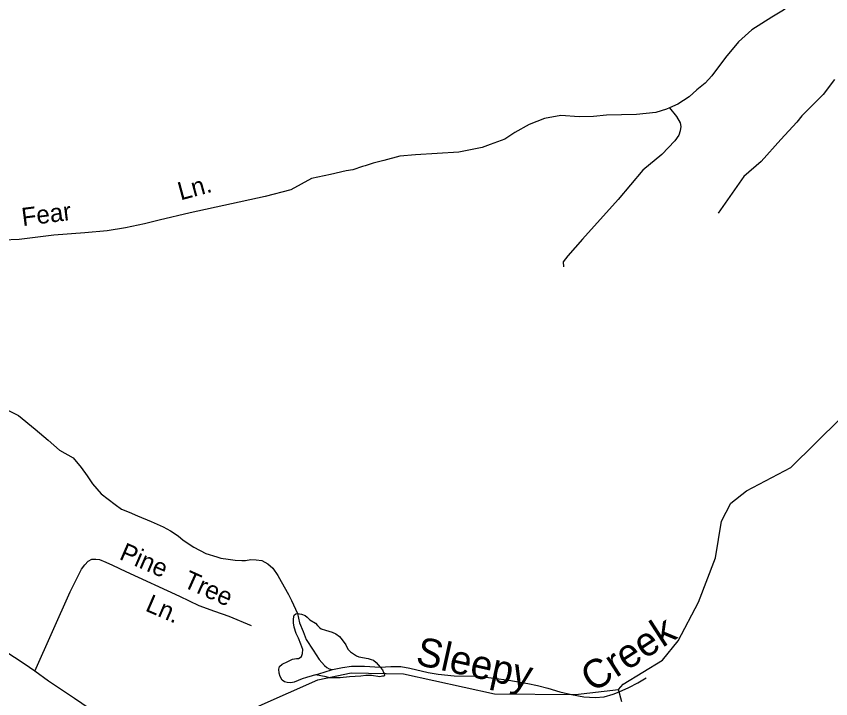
# Model space of a CAD drawing. Extents: x 2206922 to 2357709, y 510027 to 673830.
# Drawn here: x 2305011 to 2309278, y 544730 to 548303 of the extents above; entities that cross this region are included whole.
import ezdxf

# ---------------------------------------------------------------- set-up
doc = ezdxf.new("R2010")
doc.units = 0
for name, color, linetype in [('Exist Hydrographic Creek Single Shore', 7, 'Continuous'), ('Exist Hydrographic Creek Single Shore Label', 7, 'Continuous'), ('Exist Hydrographic Misc Water Feature', 7, 'Continuous'), ('Exist Road Non-System Type 51', 7, 'Continuous'), ('Exist Road Non-System Type 51 Label', 7, 'Continuous'), ('Exist Road Secondary Type 51 Attributed', 7, 'Continuous')]:
    doc.layers.add(name, color=color, linetype=linetype)

msp = doc.modelspace()

# ---------------------------------------------------------------- linework, layer by layer
at = {"layer": 'Exist Hydrographic Creek Single Shore'}
for points in [[(2308166.3, 544778), (2308190.3, 544805.2), (2308397.2, 544931.7), (2308479.2, 545033.4), (2308586.3, 545234.6), (2308675.3, 545467.9), (2308706.2, 545659.5), (2308755.2, 545753.3), (2308837.2, 545819), (2309069.4, 545939.9), (2309589.4, 546453.1), (2309837.3, 546555.1), (2310129.3, 546556.9), (2310470.3, 546544.5), (2311010.4, 546668), (2311276.3, 546760.7), (2311326.4, 546762.7)], [(2305660.2, 543918.8), (2305708.2, 544061.9), (2305749.2, 544135.7), (2305947.2, 544347.2), (2305987.2, 544440.7), (2306284.1, 544692.2), (2306591.3, 544829.3), (2306766.2, 544865.8), (2307040.2, 544860.5), (2307516.3, 544755), (2307941.2, 544752.4), (2308166.3, 544778)]]:
    msp.add_lwpolyline(points, dxfattribs=at)
at = {"layer": 'Exist Hydrographic Misc Water Feature'}
for points in [[(2304908.2, 546271), (2305022.7, 546212.4), (2305111, 546141.5), (2305178.1, 546084.4), (2305238.6, 546031.1), (2305308.9, 545991.7), (2305351.4, 545940.3), (2305381.9, 545896.4), (2305410.2, 545854.8), (2305456.8, 545803.1), (2305529.3, 545746.4), (2305563.4, 545722.6), (2305603.6, 545706.9), (2305645.8, 545687.5), (2305718.4, 545658.4), (2305780.7, 545629.1), (2305818.7, 545609.6), (2305859.1, 545582), (2305885.3, 545560.2), (2305941.5, 545522.6), (2306004, 545489.7), (2306062.3, 545472), (2306082.2, 545466.1), (2306121.9, 545460.9), (2306158, 545455.1), (2306192.3, 545453.6), (2306212.2, 545453.8), (2306240.1, 545458.1), (2306267.9, 545456.4), (2306297.9, 545452.7), (2306330.1, 545436.9), (2306354.7, 545413.3), (2306381.1, 545375.7), (2306399.2, 545343.8), (2306438.1, 545276.3), (2306452.5, 545244.5), (2306484.9, 545176.8)], [(2306578.2, 544854.1), (2306562.2, 544850), (2306532.5, 544841.6), (2306508.5, 544833.4), (2306466.6, 544817), (2306449, 544812.8), (2306431, 544814.3), (2306417.2, 544818.4), (2306404.9, 544826.3), (2306394.7, 544846.1), (2306388.7, 544864), (2306386.5, 544883.8), (2306389.9, 544897.9), (2306403.9, 544910), (2306434, 544924.5), (2306459.3, 544936.5), (2306479.6, 544940.8), (2306489.4, 544940.9), (2306499.4, 544945.1), (2306505.6, 544951), (2306511.1, 544967.2), (2306512.8, 544987.3), (2306502.7, 545015.2), (2306490.4, 545047), (2306478.3, 545070.7), (2306467.9, 545104.7), (2306463.4, 545126.5), (2306463.2, 545148.4), (2306467, 545166.5), (2306475.3, 545174.6), (2306484.9, 545176.8)], [(2306484.9, 545176.8), (2306505, 545172.9), (2306525.1, 545165.5), (2306535.3, 545157.4), (2306549.1, 545143.6), (2306579.4, 545126), (2306589.7, 545114), (2306599.5, 545101.9), (2306607.9, 545096.2), (2306631.7, 545088.6), (2306665.7, 545079), (2306685.8, 545069.1), (2306704.5, 545055.4), (2306718.4, 545037.4), (2306738.3, 545011.7), (2306748.8, 544989.8), (2306762.9, 544975.9), (2306778.9, 544964.2), (2306793.5, 544954.4), (2306805.2, 544948.5), (2306855.4, 544941), (2306871.4, 544935.3), (2306883.5, 544931), (2306897.2, 544919.2), (2306907.7, 544907.6), (2306917.5, 544895.5)], [(2306484.9, 545176.8), (2306495.8, 545126.9), (2306514, 545081.1), (2306530.4, 545039.4), (2306567.1, 544983.9), (2306597.5, 544936), (2306625.8, 544904.6), (2306638.3, 544892.5), (2306650, 544886.7), (2306668, 544882.8)], [(2306668, 544882.8), (2306720.1, 544893.6), (2306767.9, 544899.8), (2306835.9, 544900.9), (2306917.5, 544895.5)], [(2306917.5, 544895.5), (2306930.1, 544881.9), (2306936, 544868), (2306940.1, 544858), (2306940.5, 544851.9), (2306936.4, 544847.7), (2306930.5, 544847.7), (2306916.1, 544843.8), (2306872.2, 544851.2), (2306842.1, 544850.9), (2306816.3, 544848.7), (2306756.8, 544843.9), (2306708.4, 544839.4), (2306680.3, 544839.2), (2306652.2, 544838.9), (2306634.4, 544844.5), (2306578.2, 544854.1)], [(2306578.2, 544854.1), (2306624.5, 544868.7), (2306668, 544882.8)], [(2306917.5, 544895.5), (2306973.7, 544898.4), (2307025.6, 544898.7), (2307073.8, 544889.4), (2307169.8, 544866.4), (2307222.1, 544859), (2307306.1, 544850), (2307427.9, 544847.1), (2307514, 544838.1), (2307592.2, 544826.8), (2307692.2, 544810.1), (2307742.1, 544798.6), (2307796.4, 544785.1), (2307858.7, 544766), (2307920.7, 544752.6), (2307984.6, 544739.3), (2308044.5, 544736), (2308090.7, 544740.4), (2308138.4, 544753.1), (2308170.6, 544765.3), (2308220.2, 544787.8), (2308268, 544812.3), (2308311.5, 544838.6)], [(2308183.3, 544713), (2308166.3, 544778)]]:
    msp.add_lwpolyline(points, dxfattribs=at)
at = {"layer": 'Exist Road Non-System Type 51'}
for points in [[(2309382.1, 548756.2), (2309364.6, 548709), (2309341.7, 548656.4), (2309312, 548610.5), (2309307.9, 548601.9), (2309285, 548573.6), (2309227.1, 548502.6), (2309185.3, 548448.6), (2309096.3, 548383.9), (2309031.6, 548335.3), (2308969.5, 548298.9), (2308865.7, 548232.8), (2308795.6, 548169.4), (2308726.8, 548087.4), (2308655.9, 547990.7), (2308620.3, 547952.3), (2308576.7, 547917.9), (2308537.1, 547881.5), (2308477.5, 547842.9), (2308433.5, 547823.3)], [(2309298.8, 547971.3), (2309238.5, 547893.5), (2309126.7, 547781.6), (2309099.8, 547748.5), (2309017, 547657.4), (2308913.5, 547543.4), (2308822.4, 547464.7), (2308687.8, 547272.1)], [(2308433.5, 547823.3), (2308417.9, 547816.3), (2308362.2, 547799.6), (2308260.2, 547788.5), (2308104.3, 547784.8), (2308034.6, 547778), (2307960.6, 547777.2), (2307864.5, 547784.3), (2307778.8, 547767.3), (2307699.2, 547736.5), (2307623.7, 547693.8), (2307570.1, 547659.2), (2307494.4, 547632.4), (2307451.3, 547616.3), (2307330, 547592), (2307103.5, 547577.1), (2307019.9, 547570.4), (2306937.6, 547548.8), (2306881, 547534), (2306839.4, 547519.4), (2306825.5, 547517.2), (2306773.7, 547498.7), (2306739.8, 547494.4), (2306658, 547475.5), (2306558.8, 547453), (2306449.6, 547395), (2306316.1, 547358.6), (2305922.4, 547273.6), (2305760.6, 547235.8), (2305682.4, 547216.9), (2305583.9, 547195.4), (2305488.2, 547179.2), (2305370.9, 547168.4), (2305207.8, 547156.2), (2305027.1, 547134.7), (2304768.9, 547123.3)], [(2308433.5, 547823.3), (2308470.5, 547777.5), (2308489.1, 547744.4), (2308493.2, 547725.7), (2308489.1, 547702.9), (2308482.9, 547680.1), (2308462.2, 547651.2), (2308393.9, 547578.7), (2308294.5, 547497.9), (2308164.1, 547344.6), (2307977.8, 547135.4), (2307901.2, 547048.4), (2307876.3, 547017.3), (2307878.4, 546990.4)], [(2305108.3, 544874), (2305293.3, 545290.1), (2305333.7, 545369.6), (2305353.9, 545408.6), (2305370, 545431.5), (2305387.5, 545450.4), (2305407.7, 545461.1), (2305427.9, 545461.1), (2305448.1, 545458.4), (2305480.4, 545445), (2305515.4, 545428.8), (2305585.4, 545396.5), (2305866, 545267.2), (2305968.3, 545218.7), (2306050.4, 545189.1), (2306124.4, 545162.2), (2306241.5, 545113.7)]]:
    msp.add_lwpolyline(points, dxfattribs=at)
at = {"layer": 'Exist Road Secondary Type 51 Attributed'}
msp.add_lwpolyline([(2305469.6, 544626.2), (2305316.9, 544731.3), (2305179.6, 544821.5), (2305108.3, 544874), (2305052.4, 544911.7), (2304951.5, 544979)], dxfattribs=at)

# ---------------------------------------------------------------- texts
at = {"layer": 'Exist Hydrographic Creek Single Shore Label'}
for s, rotation, p in [('Creek', 32.85, (2308031.6, 544759.3)), ('Sleepy', 347.5065, (2307098.1, 544910.2))]:
    msp.add_text(s, height=150, rotation=rotation, dxfattribs=at).set_placement(p)
at = {"layer": 'Exist Road Non-System Type 51 Label'}
for s, rotation, p in [('Ln.', 15.1376, (2305872.2, 547338.7)), ('Fear', 7.3042, (2305045.2, 547204.1)), ('Pine', 336.556, (2305546, 545462.4)), ('Tree', 335.8345, (2305879.9, 545317.7)), ('Ln.', 336.556, (2305682.4, 545192.4))]:
    msp.add_text(s, height=95, rotation=rotation, dxfattribs=at).set_placement(p)

doc.saveas('drawing.dxf')
